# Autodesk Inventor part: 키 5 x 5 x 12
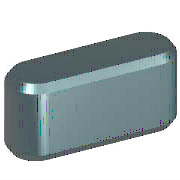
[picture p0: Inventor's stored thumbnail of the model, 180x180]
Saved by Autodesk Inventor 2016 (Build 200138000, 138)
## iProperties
Created: 2012-02
Part Number: 키 5 x 5 x 12
Material: 강철, 연강
Description: 키 및 해당 키홈
Document SubType Name: Modeling
Standard: KS B 1311
Designer: mduedu
Standards Organization: KS
Language: ko-KR
Size Designation: 5 x 5 x 12
Categories: <MemberInstance><Categories><Category DisplayName="샤프트 부품" InternalName="7f7aeb1f-a693-4053-b835-cee3144e0d98" Mnemonic="SHFT"><Category DisplayName="키" Interna
Density: 1 g/cm^3
Appearance: 노란색
IsCustomPart: 1
Author: mduedu
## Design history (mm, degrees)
workplane "Work Plane1"
workplane "Work Plane2"
sketch "스케치1"
  geometry: L1 (2.5, 2.5)-(9.5, 2.5); L2 (9.5, -2.5)-(2.5, -2.5); L3 (0, 9.4)-(0, -7.4) reference; L4 (-5, 0)-(30, 0) reference; L5 (12, 0)-(12, 7); A1 r 2.5 centre (2.5, 0) between (2.5, 2.5) and (2.5, -2.5); A2 r 2.5 centre (9.5, 0) between (9.5, -2.5) and (9.5, 2.5)
  constraints: 6 end point, 5 point on circle, 4 tangent, 3 point on line, 2 centre point, 1 horizontal, 1 parallel, 1 perpendicular
  dimensions: "d0" = 2.5 radius of A1 (= 0.5 x PB); "d13" = 2.5 radius of A2 (= 0.5 x PB); "d14" = 12 distance between parallel lines of L5 L3 (= NLG)
extrude "본체1" new body sketch "스케치1" taper "d3" = 0 deg; stored distance "d4" = 10
workplane "Work Plane3"
body "Solid1"
chamfer "모따기1" distance "d8" = 0.4 (= PHH); stored, may be unused: second distance "d9" = 0.4 (= PHH), angle "d15" = 45 deg
other parameters: "d1" = -3 (= -PNT), "d2" = 2 (= PH - PNT), "NLG" = 12 [user parameter; used in 3 equation terms], "PB" = 5 [user parameter; used in 2 equation terms], "PNT" = 3 [user parameter; used in 2 equation terms], "PH" = 5 [user parameter; used in 1 equation term], "PHH" = 0.4 [user parameter; used in 2 equation terms], "d10" = 0, "d16" = 0, "d17" = 0, "d18" = 0, "WDMIN" = 12 [user parameter], "PLB2" = 12 (= NLG) [user parameter], "WDMAX" = 17 [user parameter], "PLB1" = 12 (= NLG) [user parameter], "RR" = 0.16 [user parameter], "PUEB" = 2.3 [user parameter]
